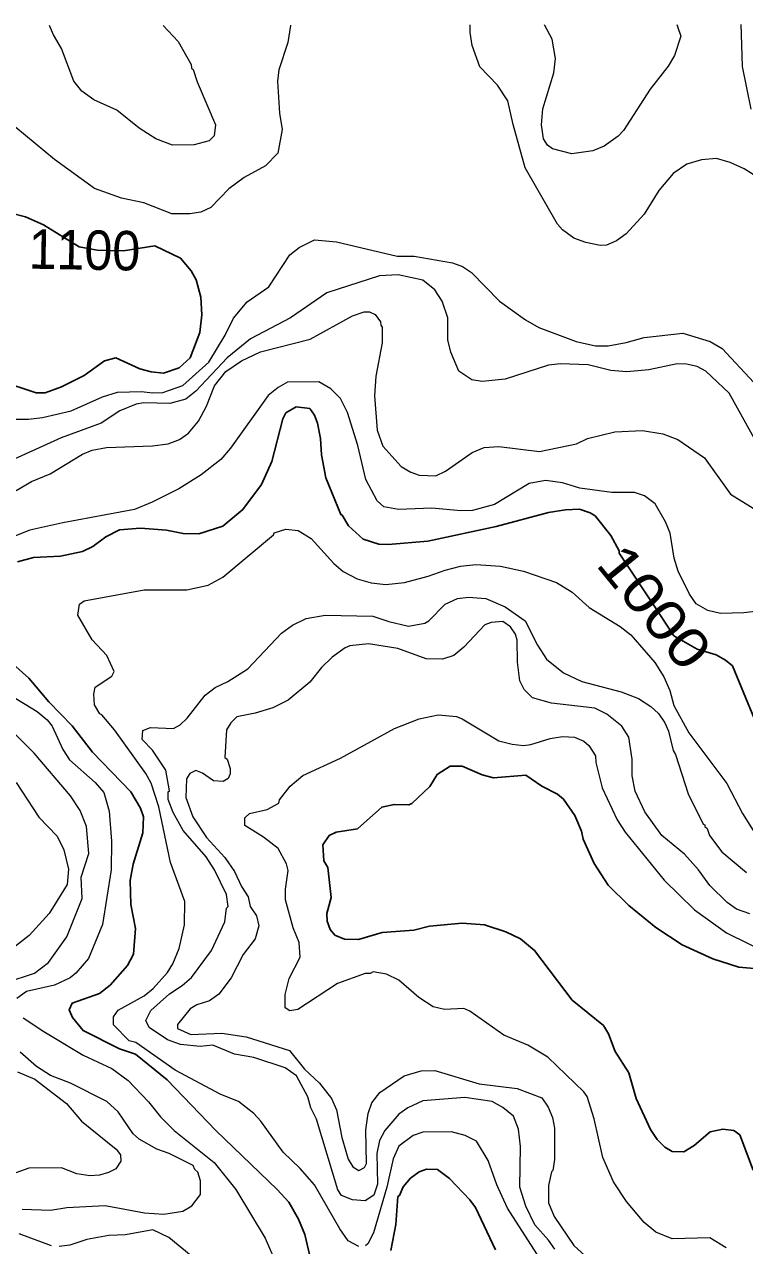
# Model space of a CAD drawing. Extents: x 447.8 to 473.9, y 7733.1 to 7760.8.
# Drawn here: x 470.364 to 471.824, y 7758.328 to 7760.802 of the extents above; entities that cross this region are included whole.
import ezdxf
from ezdxf.enums import TextEntityAlignment as Align

# ---------------------------------------------------------------- set-up
doc = ezdxf.new("R2010")
doc.units = 0
doc.header["$LTSCALE"] = 0.032
doc.layers.add('1', color=7, linetype='Continuous', lineweight=25)
doc.layers.add('2', color=7, linetype='Continuous', lineweight=13)
doc.layers.add('61', color=7, linetype='Continuous')

msp = doc.modelspace()

# ---------------------------------------------------------------- linework, layer by layer
at = {"layer": '1'}
for points in [[(470.3133, 7760.0796), (470.3873, 7760.0554), (470.4062, 7760.0557), (470.4392, 7760.0676), (470.4847, 7760.0905), (470.5259, 7760.1202), (470.5491, 7760.1266), (470.5976, 7760.1041), (470.6205, 7760.0979), (470.6461, 7760.0955), (470.6776, 7760.1064), (470.6998, 7760.1262), (470.7196, 7760.178), (470.7238, 7760.2137), (470.7214, 7760.2493), (470.7118, 7760.2846), (470.702, 7760.3025), (470.6805, 7760.3286), (470.6285, 7760.3534), (470.5645, 7760.343), (470.5112, 7760.3447), (470.4751, 7760.3516), (470.4022, 7760.3957), (470.366, 7760.4121), (470.334, 7760.42)], [(470.3501, 7759.7128), (470.3821, 7759.7218), (470.4368, 7759.7244), (470.4813, 7759.7338), (470.5023, 7759.7442), (470.5286, 7759.7637), (470.5566, 7759.7779), (470.5992, 7759.7812), (470.6521, 7759.7771), (470.6858, 7759.7707), (470.7174, 7759.77), (470.7658, 7759.7854), (470.807, 7759.8194), (470.8443, 7759.8696), (470.8655, 7759.9167), (470.8876, 7760.0026), (470.894, 7760.015), (470.915, 7760.0272), (470.9422, 7760.024), (470.9517, 7760.0101), (470.958, 7759.9941), (470.9642, 7759.9631), (470.966, 7759.93), (470.9752, 7759.8836), (471.0052, 7759.8088), (471.0083, 7759.8075), (471.0207, 7759.7858), (471.0505, 7759.7589)], [(471.0505, 7759.7589), (471.0826, 7759.7492), (471.1013, 7759.7484), (471.1815, 7759.7551), (471.3206, 7759.7845), (471.4264, 7759.8133)], [(471.4264, 7759.8133), (471.461, 7759.8188), (471.4891, 7759.8195), (471.5111, 7759.8127), (471.5212, 7759.8062), (471.5529, 7759.7664), (471.57, 7759.7353), (471.5699, 7759.7309), (471.642, 7759.6216), (471.6805, 7759.5633), (471.7281, 7759.536), (471.7662, 7759.5245), (471.7857, 7759.5139), (471.7993, 7759.5024), (471.8445, 7759.3945)], [(470.9425, 7758.3065), (470.9321, 7758.3499), (470.9196, 7758.3813), (470.9, 7758.4156), (470.8764, 7758.4415), (470.7522, 7758.5609), (470.6535, 7758.6636), (470.5892, 7758.7158), (470.5568, 7758.7265), (470.4828, 7758.7631), (470.4615, 7758.79), (470.4547, 7758.8053), (470.4605, 7758.8186), (470.5163, 7758.8383), (470.5374, 7758.8556), (470.5731, 7758.8954), (470.5851, 7758.9184), (470.5892, 7758.9704), (470.5795, 7759.0185), (470.5779, 7759.0675), (470.5846, 7759.1006), (470.6036, 7759.164), (470.6052, 7759.1961), (470.5993, 7759.2142), (470.5793, 7759.2468), (470.5016, 7759.3275), (470.4607, 7759.3807), (470.4131, 7759.4291), (470.3725, 7759.4776), (470.3274, 7759.518)], [(471.8416, 7758.4804), (471.8143, 7758.5517), (471.802, 7758.561), (471.7803, 7758.5636), (471.7542, 7758.5583), (471.722, 7758.5303), (471.7008, 7758.5178), (471.6774, 7758.5181), (471.6624, 7758.5267), (471.6466, 7758.5425), (471.6336, 7758.5626), (471.6044, 7758.6253), (471.5895, 7758.6774), (471.562, 7758.7206), (471.5481, 7758.7569), (471.538, 7758.7738), (471.4747, 7758.8252), (471.3982, 7758.9256), (471.3696, 7758.9493), (471.3399, 7758.9634), (471.297, 7758.9778), (471.2511, 7758.9812), (471.1849, 7758.9747), (471.1532, 7758.9667), (471.0895, 7758.9619), (471.041, 7758.9475), (471.0128, 7758.9483), (470.9933, 7758.9564), (470.9837, 7758.9682), (470.9779, 7758.9852), (470.9772, 7759.0007), (470.9859, 7759.0329), (470.9791, 7759.0937), (470.9706, 7759.1071), (470.9692, 7759.1396), (470.982, 7759.1583), (470.9957, 7759.1652), (471.039, 7759.1719), (471.0882, 7759.2161), (471.1134, 7759.2214), (471.1431, 7759.2209), (471.1494, 7759.2234), (471.1857, 7759.258), (471.2008, 7759.2825), (471.2273, 7759.2993), (471.2517, 7759.2993), (471.2922, 7759.2812), (471.3151, 7759.2755), (471.3805, 7759.2809), (471.4129, 7759.2586), (471.4446, 7759.2425), (471.4571, 7759.2322), (471.4799, 7759.1989), (471.4932, 7759.1675), (471.4968, 7759.1508), (471.5189, 7759.1017), (471.5474, 7759.0579), (471.5893, 7759.0167), (471.6443, 7758.9722), (471.6972, 7758.9372), (471.7599, 7758.9089), (471.8126, 7758.8916), (471.8598, 7758.8875)], [(471.3188, 7758.3188), (471.2785, 7758.4048), (471.2671, 7758.4204), (471.2259, 7758.4632), (471.2011, 7758.4817), (471.1792, 7758.4826), (471.164, 7758.4773), (471.1469, 7758.464), (471.132, 7758.4467), (471.1245, 7758.4291), (471.1213, 7758.427), (471.1166, 7758.3701), (471.1071, 7758.3179)]]:
    msp.add_lwpolyline(points, dxfattribs=at)
at = {"layer": '2'}
for points in [[(470.9036, 7760.8006), (470.9035, 7760.8001), (470.8979, 7760.7658), (470.8795, 7760.7101), (470.877, 7760.6874), (470.881, 7760.6226), (470.8866, 7760.5892), (470.8776, 7760.5414), (470.8527, 7760.5155), (470.8091, 7760.4916), (470.7781, 7760.4687), (470.7421, 7760.4309), (470.7217, 7760.422), (470.6994, 7760.4185), (470.6624, 7760.4181), (470.6057, 7760.4405), (470.5608, 7760.4501), (470.5061, 7760.4696), (470.4248, 7760.5282), (470.3265, 7760.6097)], [(470.6454, 7760.8001), (470.6755, 7760.7674), (470.7022, 7760.7206), (470.7027, 7760.7134), (470.7062, 7760.7107), (470.714, 7760.686), (470.7511, 7760.5988), (470.7486, 7760.5761), (470.7386, 7760.5665), (470.7083, 7760.5578), (470.664, 7760.5572), (470.6303, 7760.5703), (470.5966, 7760.5921), (470.5509, 7760.6281), (470.5045, 7760.6492), (470.4803, 7760.6669), (470.4642, 7760.687), (470.4392, 7760.753), (470.4226, 7760.7813), (470.4144, 7760.7997)], [(471.86, 7760.4864), (471.823, 7760.5093), (471.7951, 7760.5225), (471.767, 7760.5304), (471.7367, 7760.5274), (471.7067, 7760.5187), (471.6791, 7760.4999), (471.6501, 7760.4659), (471.6203, 7760.4176), (471.5842, 7760.3779), (471.5645, 7760.3633), (471.5438, 7760.3545), (471.5311, 7760.3544), (471.5019, 7760.3604), (471.4779, 7760.3692), (471.4551, 7760.3856), (471.4444, 7760.3971), (471.3793, 7760.5113), (471.3547, 7760.5992), (471.3442, 7760.6472), (471.3232, 7760.6789), (471.287, 7760.7161), (471.2718, 7760.7591), (471.2674, 7760.786), (471.2674, 7760.8012)], [(471.6868, 7760.8019), (471.6882, 7760.7977), (471.6946, 7760.7783), (471.6822, 7760.7393), (471.6691, 7760.7177), (471.6327, 7760.6707), (471.5783, 7760.5874), (471.5679, 7760.5758), (471.5395, 7760.5554), (471.5164, 7760.5461), (471.4738, 7760.5396), (471.4346, 7760.5498), (471.4243, 7760.5573), (471.4163, 7760.5702), (471.4125, 7760.5985), (471.4149, 7760.6313), (471.4371, 7760.7043), (471.4404, 7760.7331), (471.434, 7760.7719), (471.4189, 7760.8001), (471.4182, 7760.8014)], [(471.8166, 7760.8021), (471.8173, 7760.7824), (471.8195, 7760.7169), (471.8365, 7760.6304)], [(470.3204, 7760.0025), (470.3718, 7760.0025), (470.4007, 7760.0057), (470.4588, 7760.0188), (470.5218, 7760.0475), (470.5524, 7760.0569), (470.601, 7760.0586), (470.6238, 7760.0554), (470.6442, 7760.056), (470.6849, 7760.0703), (470.7376, 7760.1176), (470.771, 7760.1722), (470.7877, 7760.207), (470.8158, 7760.2402), (470.8594, 7760.2705), (470.902, 7760.3352), (470.9211, 7760.3503), (470.952, 7760.3655), (470.9968, 7760.3615), (471.1195, 7760.3327), (471.1542, 7760.3325), (471.2317, 7760.3191), (471.2521, 7760.3114), (471.2703, 7760.2992), (471.3269, 7760.2414), (471.3796, 7760.2036), (471.4066, 7760.1878), (471.4827, 7760.1599), (471.5219, 7760.1508), (471.5477, 7760.1511), (471.5837, 7760.1573), (471.6204, 7760.1676), (471.6986, 7760.1763), (471.7541, 7760.1598), (471.7786, 7760.1452), (471.8431, 7760.0767)], [(471.847, 7759.9576), (471.7925, 7760.0549), (471.7458, 7760.0994), (471.7279, 7760.1092), (471.7063, 7760.1139), (471.6873, 7760.1146), (471.6301, 7760.1024), (471.5852, 7760.0979), (471.5527, 7760.101), (471.5071, 7760.1123), (471.451, 7760.1146), (471.4266, 7760.1115), (471.3384, 7760.0832), (471.292, 7760.0785), (471.271, 7760.0819), (471.2449, 7760.0998), (471.2283, 7760.1377), (471.2225, 7760.1628), (471.2224, 7760.2073), (471.2111, 7760.2416), (471.1958, 7760.264), (471.1719, 7760.2838), (471.1214, 7760.295), (471.0836, 7760.2927), (470.9769, 7760.258), (470.9035, 7760.2075), (470.8222, 7760.1647), (470.7749, 7760.1264)], [(470.3469, 7759.8578), (470.3779, 7759.8759), (470.4158, 7759.8917), (470.4816, 7759.931), (470.5013, 7759.9392), (470.5302, 7759.9448), (470.6235, 7759.948), (470.6554, 7759.9525), (470.6784, 7759.9612), (470.6963, 7759.974), (470.7167, 7759.9982), (470.7328, 7760.0284), (470.7489, 7760.0697), (470.7722, 7760.0989), (470.8038, 7760.1205), (470.8422, 7760.1386), (470.9429, 7760.1641), (471.0291, 7760.2117), (471.0526, 7760.2196), (471.0634, 7760.2196), (471.0749, 7760.214), (471.0859, 7760.1995), (471.0862, 7760.1928), (471.0894, 7760.1889), (471.0895, 7760.1567), (471.0766, 7760.0893), (471.0734, 7760.0493), (471.079, 7759.9797), (471.0907, 7759.9478), (471.1277, 7759.9066), (471.1472, 7759.8949), (471.1644, 7759.8887), (471.1981, 7759.8871), (471.2179, 7759.8968), (471.2715, 7759.9346), (471.2962, 7759.9447), (471.3257, 7759.9471), (471.4084, 7759.9368), (471.4835, 7759.9523), (471.5057, 7759.9627), (471.5611, 7759.9768), (471.6172, 7759.9792), (471.6582, 7759.9728), (471.6889, 7759.9607), (471.7427, 7759.9237), (471.7954, 7759.8504), (471.8765, 7759.8004)], [(470.7749, 7760.1264), (470.7116, 7760.0591), (470.6912, 7760.043), (470.6588, 7760.0338), (470.6057, 7760.0354), (470.5905, 7760.0328)], [(470.8783, 7760.0666), (470.8583, 7760.0503), (470.7818, 7759.9434), (470.7621, 7759.9204), (470.7225, 7759.8893), (470.6767, 7759.861)], [(471.8749, 7759.616), (471.8225, 7759.61), (471.7755, 7759.6085), (471.7493, 7759.6147), (471.7261, 7759.6281), (471.7126, 7759.6475), (471.6893, 7759.6941), (471.6814, 7759.7204), (471.6729, 7759.7715), (471.664, 7759.7943), (471.6425, 7759.8307), (471.621, 7759.8467), (471.6008, 7759.8533), (471.5552, 7759.8534), (471.4903, 7759.8626), (471.4546, 7759.8734), (471.4205, 7759.8782), (471.3872, 7759.8716), (471.3167, 7759.8292), (471.2725, 7759.8173), (471.2486, 7759.8165), (471.1899, 7759.8221), (471.1224, 7759.8189), (471.0929, 7759.8248), (471.079, 7759.8367), (471.056, 7759.88), (471.0402, 7759.949), (471.0186, 7760.0159), (471.0046, 7760.0439), (470.9849, 7760.0635), (470.9609, 7760.0777), (470.8973, 7760.0769), (470.8783, 7760.0666)], [(470.5905, 7760.0328), (470.5574, 7760.0194), (470.5195, 7759.9939), (470.4382, 7759.9646), (470.3208, 7759.9108)], [(470.6767, 7759.861), (470.623, 7759.8341), (470.5869, 7759.8194), (470.4414, 7759.7924), (470.3751, 7759.7774), (470.3253, 7759.7574)], [(471.0416, 7758.326), (471.0204, 7758.3373), (471.0034, 7758.3613), (470.9521, 7758.4508), (470.9232, 7758.4837), (470.8885, 7758.5169), (470.8431, 7758.5799), (470.829, 7758.5954), (470.7976, 7758.6197), (470.7621, 7758.6334), (470.6696, 7758.6829), (470.5895, 7758.7389), (470.5765, 7758.7428), (470.5443, 7758.7749), (470.5444, 7758.7908), (470.5538, 7758.8045), (470.6063, 7758.834), (470.6246, 7758.8486), (470.6536, 7758.8812), (470.6647, 7758.8982), (470.6773, 7758.9299), (470.6885, 7758.9777), (470.6894, 7759.0245), (470.66, 7759.1039), (470.6366, 7759.2166), (470.6206, 7759.2646), (470.6103, 7759.2844), (470.5465, 7759.3727), (470.521, 7759.4034), (470.5168, 7759.405), (470.5059, 7759.4232), (470.5043, 7759.4449), (470.5074, 7759.4594), (470.5408, 7759.4813), (470.5458, 7759.491), (470.5306, 7759.5235), (470.5013, 7759.5549), (470.4722, 7759.6052), (470.4752, 7759.6274), (470.4848, 7759.6343), (470.6066, 7759.6563), (470.6931, 7759.6561), (470.7364, 7759.6656), (470.7661, 7759.6823), (470.8686, 7759.7675), (470.8701, 7759.7716), (470.8936, 7759.7796), (470.9191, 7759.7768), (470.9451, 7759.7603), (470.9913, 7759.7094), (471.0098, 7759.6933), (471.0385, 7759.6785), (471.0666, 7759.6706), (471.0966, 7759.6674), (471.1344, 7759.6713), (471.1826, 7759.6838)], [(471.1826, 7759.6838), (471.2168, 7759.6964), (471.2482, 7759.7042), (471.2793, 7759.7074), (471.329, 7759.7041), (471.376, 7759.6939)], [(471.376, 7759.6939), (471.4426, 7759.6715), (471.4746, 7759.6515), (471.5089, 7759.6209), (471.5719, 7759.5819), (471.5933, 7759.565), (471.6422, 7759.5089), (471.6601, 7759.4798), (471.6724, 7759.4522), (471.6803, 7759.4218), (471.7111, 7759.3663), (471.7879, 7759.264), (471.82, 7759.2033), (471.8516, 7759.1523)], [(471.2171, 7759.6275), (471.2418, 7759.6385), (471.2642, 7759.6418), (471.2991, 7759.6386), (471.3389, 7759.622), (471.3792, 7759.5936), (471.4043, 7759.5442), (471.4227, 7759.5161), (471.457, 7759.4885), (471.4941, 7759.4705), (471.5736, 7759.4498), (471.609, 7759.436), (471.6339, 7759.4202), (471.6494, 7759.4057), (471.6625, 7759.3868), (471.67, 7759.3702), (471.6794, 7759.3308), (471.684, 7759.323), (471.7096, 7759.2432), (471.74, 7759.1814), (471.7434, 7759.1805), (471.7437, 7759.1766), (471.7483, 7759.1728), (471.7532, 7759.1585), (471.7782, 7759.1253), (471.8279, 7759.0834)], [(471.0701, 7759.6032), (471.1028, 7759.5919), (471.1426, 7759.5825), (471.1759, 7759.5889), (471.1837, 7759.5935), (471.2171, 7759.6275)], [(471.439, 7758.3201), (471.4266, 7758.3386), (471.3985, 7758.3694), (471.3802, 7758.4076), (471.3684, 7758.4458), (471.37, 7758.5281), (471.3654, 7758.5633), (471.3555, 7758.5897), (471.3336, 7758.6075), (471.3125, 7758.6196), (471.2571, 7758.6277), (471.1714, 7758.6206), (471.1412, 7758.6069), (471.1231, 7758.594), (471.0944, 7758.5606), (471.0838, 7758.5402), (471.0781, 7758.5139), (471.0797, 7758.4521), (471.0722, 7758.4298), (471.055, 7758.4186), (471.0291, 7758.42), (471.0065, 7758.4288), (470.9992, 7758.4404), (470.9562, 7758.5839), (470.9449, 7758.6067), (470.9386, 7758.6288), (470.9157, 7758.6714), (470.8922, 7758.6878), (470.8293, 7758.7087), (470.7896, 7758.7156), (470.746, 7758.7335), (470.7201, 7758.7312), (470.6806, 7758.7348), (470.6536, 7758.7446), (470.617, 7758.7694), (470.6102, 7758.7835), (470.6203, 7758.8038), (470.6582, 7758.8379), (470.6836, 7758.8544), (470.7025, 7758.871), (470.7433, 7758.9258), (470.7701, 7758.9838), (470.7736, 7759.0112), (470.7766, 7759.0146), (470.7734, 7759.0392), (470.7491, 7759.0893), (470.7322, 7759.1155), (470.6859, 7759.169), (470.6656, 7759.2049), (470.655, 7759.2316), (470.655, 7759.2471), (470.6581, 7759.2493), (470.6505, 7759.2912), (470.6238, 7759.3313), (470.6023, 7759.3531), (470.6036, 7759.3713), (470.6197, 7759.3772), (470.6661, 7759.3757), (470.6795, 7759.3827), (470.6941, 7759.3964), (470.7301, 7759.4427), (470.7506, 7759.4586), (470.776, 7759.4706), (470.8166, 7759.4965), (470.8852, 7759.5689), (470.9077, 7759.585), (470.9354, 7759.5981), (470.9736, 7759.6048), (471.0701, 7759.6032)], [(471.8348, 7759), (471.8079, 7759.0091), (471.7885, 7759.0229), (471.7539, 7759.0574), (471.7304, 7759.0889), (471.7021, 7759.1205), (471.6564, 7759.1589), (471.6221, 7759.2065), (471.6025, 7759.2486), (471.5961, 7759.2795), (471.596, 7759.3134), (471.5896, 7759.3576), (471.5753, 7759.3802), (471.5449, 7759.4041), (471.5203, 7759.4165), (471.4326, 7759.4266), (471.3943, 7759.4373), (471.3774, 7759.4542), (471.3684, 7759.4722), (471.3636, 7759.5095), (471.3628, 7759.5544), (471.3595, 7759.5663), (471.3492, 7759.5816), (471.3336, 7759.5925), (471.3103, 7759.5903), (471.2975, 7759.5852), (471.2551, 7759.5405), (471.2346, 7759.523), (471.2116, 7759.5159), (471.1782, 7759.5165), (471.1209, 7759.5372), (471.0615, 7759.5471), (471.0236, 7759.5431), (471.014, 7759.5391), (470.9879, 7759.5202), (470.9659, 7759.4991), (470.9425, 7759.4691), (470.8989, 7759.4327), (470.8675, 7759.417), (470.8319, 7759.4062), (470.7947, 7759.3993)], [(470.2848, 7759.4733), (470.3898, 7759.4096), (470.4102, 7759.3927), (470.4202, 7759.3801), (470.4416, 7759.3326), (470.455, 7759.3122), (470.5073, 7759.2659), (470.5248, 7759.2458), (470.5354, 7759.2079), (470.5404, 7759.1471), (470.5395, 7759.0887), (470.5218, 7758.9781), (470.4934, 7758.9091), (470.4682, 7758.8796), (470.4564, 7758.87), (470.4247, 7758.8556), (470.368, 7758.8425), (470.3485, 7758.8283)], [(470.7947, 7759.3993), (470.7823, 7759.387), (470.7736, 7759.3724), (470.7703, 7759.3167), (470.7746, 7759.3131), (470.7807, 7759.2946)], [(470.8108, 7759.1947), (470.8199, 7759.2034), (470.8563, 7759.2113), (470.8796, 7759.2239), (470.8812, 7759.2307), (470.9024, 7759.2583), (470.9285, 7759.2804), (471.0048, 7759.3152), (471.114, 7759.3755), (471.1644, 7759.3947), (471.2025, 7759.4028), (471.2398, 7759.3997), (471.2517, 7759.3953), (471.326, 7759.3503), (471.3527, 7759.3435), (471.376, 7759.3412), (471.3905, 7759.3427), (471.4299, 7759.3549), (471.4546, 7759.3595), (471.4792, 7759.3578), (471.4979, 7759.35), (471.508, 7759.3409), (471.522, 7759.3198), (471.5223, 7759.3063), (471.5352, 7759.255), (471.5659, 7759.1906), (471.582, 7759.165), (471.6612, 7759.0682), (471.7224, 7759.0079), (471.7877, 7758.9615), (471.8778, 7758.9165)], [(470.3268, 7758.8607), (470.3843, 7758.8796), (470.4128, 7758.901), (470.4499, 7758.9534), (470.481, 7759.0307), (470.4786, 7759.0738), (470.4945, 7759.122), (470.4899, 7759.177), (470.4767, 7759.2091), (470.4571, 7759.2391), (470.3834, 7759.3257), (470.3429, 7759.3661)], [(470.7807, 7759.2946), (470.7807, 7759.2838), (470.7768, 7759.2743), (470.7668, 7759.2682), (470.747, 7759.2696), (470.7246, 7759.285), (470.7111, 7759.2905), (470.6993, 7759.2844), (470.6926, 7759.2732), (470.6909, 7759.2356), (470.7053, 7759.1963), (470.7333, 7759.1546), (470.7705, 7759.114), (470.7896, 7759.0854), (470.8038, 7759.0555), (470.8174, 7759.0344), (470.8217, 7759.015), (470.8345, 7758.9956), (470.8393, 7758.9757), (470.8318, 7758.9489), (470.8072, 7758.9171), (470.7828, 7758.87), (470.7581, 7758.8368), (470.7391, 7758.8234), (470.7133, 7758.8156), (470.7002, 7758.8074), (470.6744, 7758.7755), (470.6745, 7758.7672), (470.7015, 7758.7552), (470.7643, 7758.7583), (470.8133, 7758.7504), (470.9015, 7758.7232), (470.9315, 7758.6853), (470.9619, 7758.6565), (470.9868, 7758.6253), (470.9964, 7758.6028), (471.0077, 7758.5464), (471.0202, 7758.5025), (471.03, 7758.4869), (471.0421, 7758.4797), (471.0537, 7758.4855), (471.0573, 7758.4938), (471.0558, 7758.5619), (471.0606, 7758.5951), (471.0682, 7758.6167), (471.0843, 7758.6379), (471.134, 7758.6717), (471.168, 7758.6814), (471.1962, 7758.6823), (471.2856, 7758.6556), (471.3632, 7758.6462), (471.4131, 7758.6269), (471.426, 7758.6084), (471.4345, 7758.5868), (471.4389, 7758.5657), (471.4388, 7758.5018), (471.4356, 7758.4798), (471.4325, 7758.4767), (471.4262, 7758.4496), (471.4264, 7758.4143), (471.4379, 7758.3867), (471.478, 7758.3277), (471.5084, 7758.3001)], [(470.3469, 7759.266), (470.3932, 7759.1955), (470.4301, 7759.1569), (470.4439, 7759.1294), (470.4529, 7759.0902), (470.4506, 7759.059), (470.414, 7759.0006), (470.3732, 7758.956), (470.3303, 7758.922)], [(470.8986, 7759.0875), (470.8954, 7759.1011), (470.8785, 7759.1319), (470.8487, 7759.1553), (470.8109, 7759.179), (470.8108, 7759.1947)], [(471.7865, 7758.3231), (471.7536, 7758.3432), (471.6774, 7758.3416), (471.6439, 7758.3545), (471.6203, 7758.3742), (471.5845, 7758.4172), (471.5585, 7758.4565), (471.5368, 7758.5064), (471.5194, 7758.5841), (471.5048, 7758.6295), (471.498, 7758.6391), (471.4254, 7758.7091), (471.3847, 7758.7334), (471.3356, 7758.7539), (471.2667, 7758.8027), (471.2545, 7758.8079), (471.2157, 7758.8057), (471.1927, 7758.8117), (471.1634, 7758.8303), (471.1228, 7758.8652), (471.0979, 7758.8774), (471.0707, 7758.8825), (471.0646, 7758.8787), (471.0545, 7758.8786), (470.9983, 7758.8587), (470.9181, 7758.8058), (470.9022, 7758.8033), (470.8925, 7758.8096), (470.8923, 7758.8366), (470.9003, 7758.869), (470.9227, 7758.9117), (470.921, 7758.9416), (470.9089, 7758.9713), (470.8931, 7759.028), (470.893, 7759.0498), (470.8986, 7759.0875)], [(470.3611, 7758.7893), (470.4029, 7758.7611), (470.4827, 7758.7135), (470.5409, 7758.6864), (470.5745, 7758.6624), (470.6154, 7758.6192), (470.6395, 7758.5887), (470.6674, 7758.5609), (470.7488, 7758.4961), (470.7924, 7758.4415), (470.8519, 7758.3425), (470.8742, 7758.2913)], [(470.3592, 7758.4017), (470.4167, 7758.3993), (470.45, 7758.4049), (470.5274, 7758.4089), (470.607, 7758.3941), (470.6466, 7758.3913), (470.685, 7758.3974), (470.703, 7758.4082), (470.7206, 7758.4309), (470.7206, 7758.4586), (470.7157, 7758.4762), (470.7092, 7758.4816), (470.7059, 7758.4898), (470.6574, 7758.514), (470.632, 7758.523), (470.5966, 7758.5432), (470.5845, 7758.5541), (470.5537, 7758.5983), (470.5309, 7758.6193), (470.457, 7758.6566), (470.4169, 7758.6721), (470.388, 7758.6902), (470.3554, 7758.7197)], [(470.3498, 7758.6797), (470.3851, 7758.665), (470.4489, 7758.6157), (470.4798, 7758.58), (470.5495, 7758.5232), (470.5585, 7758.5117), (470.5595, 7758.4989), (470.5489, 7758.4833), (470.5346, 7758.4755), (470.5159, 7758.4705), (470.4967, 7758.4691), (470.47, 7758.4728), (470.4392, 7758.4849), (470.3728, 7758.4842), (470.3388, 7758.4722)], [(471.4147, 7758.2921), (471.3431, 7758.4033), (471.3216, 7758.4508), (471.3044, 7758.4999), (471.2802, 7758.5392), (471.2577, 7758.5507), (471.2296, 7758.5578), (471.1719, 7758.5572), (471.1518, 7758.5509), (471.1233, 7758.5292), (471.1115, 7758.5037), (471.0987, 7758.446), (471.0714, 7758.3535), (471.0601, 7758.3308), (471.0552, 7758.327)], [(470.419, 7758.3272), (470.3532, 7758.3515)], [(470.7016, 7758.3067), (470.6568, 7758.3438), (470.6241, 7758.3592), (470.569, 7758.3496), (470.5347, 7758.3479), (470.4902, 7758.34), (470.4558, 7758.3287), (470.4341, 7758.3256)]]:
    msp.add_lwpolyline(points, dxfattribs=at)

# ---------------------------------------------------------------- texts
at = {"layer": '61'}
for s, rotation, width, p in [('1100', 358.96, 0.95, (470.4849, 7760.3052)), ('1000', 309.226, 1.2, (471.6107, 7759.5967))]:
    msp.add_text(s, height=0.08, rotation=rotation, dxfattribs=dict(at, width=width)).set_placement(p, align=Align.CENTER)

doc.saveas('drawing.dxf')
